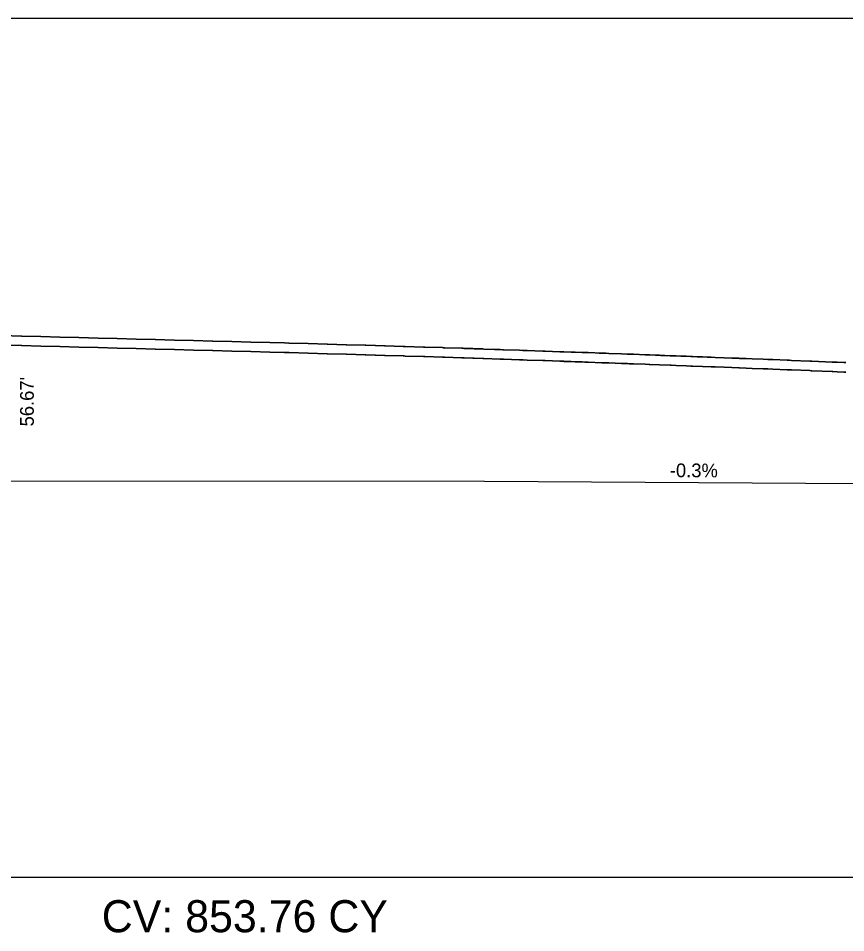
# Model space of a CAD drawing. Extents: x -26 to 4403, y -13 to 9578.
# Drawn here: x 1306.82 to 1350.15, y 6997.1 to 7045 of the extents above; entities that cross this region are included whole.
import ezdxf

# ---------------------------------------------------------------- set-up
doc = ezdxf.new("R2010")
doc.units = 0
for name, color, linetype in [('CONST_LV3', 7, 'Continuous'), ('DTM_P_FINISHED_GRADE', 7, 'Continuous'), ('DTM_X_GROUND', 7, 'Continuous'), ('XS_CELL', 7, 'Continuous'), ('XS_M_SHAPES_EARTHWORK', 7, 'Continuous'), ('XS_P_DR_GRAVEL', 7, 'Continuous'), ('XS_P_GROUND', 7, 'Continuous'), ('XS_P_TX_CLEARZONE', 7, 'Continuous'), ('XS_P_TX_FS_BS', 7, 'Continuous'), ('XS_SHEET_EW_TX_VOLUME', 7, 'Continuous')]:
    doc.layers.add(name, color=color, linetype=linetype)

msp = doc.modelspace()

# ---------------------------------------------------------------- linework, layer by layer
at = {"layer": 'CONST_LV3'}
msp.add_lwpolyline([(1305.996, 7028.38), (1306.996, 7028.354), (1307.996, 7028.327), (1308.996, 7028.301), (1309.996, 7028.274), (1310.996, 7028.248), (1311.996, 7028.221), (1312.996, 7028.195), (1313.996, 7028.169), (1314.996, 7028.142), (1315.996, 7028.116), (1316.996, 7028.089), (1317.996, 7028.063), (1318.996, 7028.036), (1319.996, 7028.01), (1320.757, 7027.99), (1320.996, 7027.983), (1320.996, 7027.983), (1320.996, 7027.983), (1321.996, 7027.956), (1321.996, 7027.956), (1321.998, 7027.956), (1322.995, 7027.928), (1322.998, 7027.928), (1323.002, 7027.928), (1323.994, 7027.9), (1324, 7027.9), (1324.007, 7027.899), (1324.991, 7027.87), (1325.006, 7027.87), (1325.014, 7027.87), (1325.025, 7027.87), (1326.004, 7027.84), (1326.015, 7027.84), (1326.021, 7027.84), (1326.504, 7027.825), (1326.546, 7027.824), (1327.029, 7027.809), (1327.079, 7027.807), (1328.037, 7027.777), (1328.047, 7027.777), (1328.104, 7027.775), (1329.044, 7027.745), (1329.071, 7027.744), (1329.132, 7027.742), (1330.051, 7027.712), (1330.103, 7027.71), (1330.105, 7027.71), (1330.161, 7027.709), (1331.056, 7027.678), (1331.142, 7027.676), (1331.192, 7027.674), (1331.632, 7027.659), (1331.753, 7027.655), (1332.189, 7027.64), (1332.223, 7027.639), (1333.062, 7027.61), (1333.247, 7027.604), (1333.255, 7027.604), (1333.46, 7027.597), (1334.287, 7027.567), (1334.314, 7027.567), (1334.405, 7027.564), (1335.187, 7027.535), (1335.319, 7027.531), (1335.394, 7027.529), (1335.597, 7027.522), (1336.35, 7027.494), (1336.486, 7027.489), (1336.668, 7027.483), (1337.031, 7027.47), (1337.239, 7027.463), (1337.592, 7027.449), (1337.741, 7027.444), (1338.409, 7027.419), (1338.713, 7027.408), (1338.815, 7027.405), (1339.032, 7027.397), (1339.657, 7027.373), (1339.851, 7027.366), (1339.889, 7027.365), (1340.461, 7027.343), (1340.964, 7027.323), (1341.006, 7027.322), (1341.52, 7027.303), (1342.038, 7027.282), (1342.132, 7027.279), (1342.37, 7027.269), (1342.89, 7027.25), (1343.113, 7027.241), (1343.32, 7027.233), (1343.79, 7027.216), (1344.186, 7027.2), (1344.546, 7027.187), (1344.589, 7027.185), (1344.928, 7027.173), (1345.257, 7027.159), (1345.828, 7027.137), (1346.066, 7027.128), (1346.328, 7027.118), (1347.092, 7027.087), (1347.205, 7027.084), (1347.397, 7027.076), (1348.345, 7027.037), (1348.384, 7027.036), (1348.444, 7027.034), (1349.459, 7026.992), (1349.484, 7026.991), (1349.704, 7026.984), (1350.05, 7026.97), (1350.15, 7026.966)], dxfattribs=at)
at = {"layer": 'DTM_P_FINISHED_GRADE'}
msp.add_lwpolyline([(1306, 7028.38), (1306.996, 7028.354), (1307, 7028.354), (1307.996, 7028.327), (1308, 7028.327), (1308.996, 7028.301), (1309, 7028.301), (1309.996, 7028.274), (1310, 7028.274), (1310.996, 7028.248), (1311, 7028.248), (1311.996, 7028.221), (1312, 7028.221), (1312.996, 7028.195), (1313, 7028.195), (1313.996, 7028.169), (1314, 7028.168), (1314.996, 7028.142), (1315, 7028.142), (1315.996, 7028.116), (1316, 7028.115), (1316.996, 7028.089), (1317, 7028.089), (1317.996, 7028.063), (1318, 7028.063), (1318.996, 7028.036), (1319, 7028.036), (1319.996, 7028.01), (1320, 7028.01), (1320.757, 7027.99), (1320.996, 7027.983), (1320.996, 7027.983), (1321, 7027.983), (1321, 7027.983), (1321.996, 7027.956), (1321.996, 7027.956), (1322, 7027.956), (1322.002, 7027.956), (1322.995, 7027.928), (1322.998, 7027.928), (1323.001, 7027.928), (1323.005, 7027.928), (1323.994, 7027.9), (1324, 7027.9), (1324.003, 7027.899), (1324.011, 7027.899), (1324.991, 7027.87), (1325.006, 7027.87), (1325.01, 7027.87), (1325.017, 7027.87), (1325.507, 7027.855), (1325.521, 7027.855), (1326.004, 7027.84), (1326.015, 7027.84), (1326.019, 7027.84), (1326.025, 7027.84), (1326.98, 7027.81), (1327.029, 7027.809), (1327.032, 7027.809), (1327.083, 7027.807), (1328.037, 7027.777), (1328.047, 7027.777), (1328.051, 7027.777), (1328.108, 7027.775), (1329.044, 7027.745), (1329.072, 7027.744), (1329.075, 7027.744), (1329.135, 7027.742), (1330.051, 7027.712), (1330.103, 7027.71), (1330.106, 7027.71), (1330.109, 7027.71), (1330.164, 7027.708), (1330.617, 7027.693), (1330.697, 7027.691), (1331.142, 7027.676), (1331.145, 7027.676), (1331.195, 7027.674), (1332.06, 7027.644), (1332.189, 7027.64), (1332.193, 7027.64), (1332.226, 7027.639), (1333.062, 7027.61), (1333.247, 7027.604), (1333.25, 7027.604), (1333.258, 7027.604), (1333.463, 7027.597), (1334.287, 7027.567), (1334.315, 7027.567), (1334.318, 7027.567), (1334.408, 7027.564), (1335.187, 7027.535), (1335.319, 7027.531), (1335.394, 7027.529), (1335.397, 7027.528), (1335.774, 7027.515), (1335.983, 7027.507), (1336.35, 7027.494), (1336.486, 7027.489), (1336.489, 7027.489), (1336.671, 7027.483), (1337.38, 7027.456), (1337.592, 7027.449), (1337.595, 7027.449), (1337.744, 7027.444), (1338.409, 7027.419), (1338.713, 7027.408), (1338.716, 7027.408), (1338.817, 7027.405), (1339.035, 7027.397), (1339.657, 7027.373), (1339.851, 7027.366), (1339.853, 7027.366), (1339.892, 7027.365), (1340.391, 7027.345), (1340.964, 7027.323), (1341.006, 7027.322), (1341.008, 7027.322), (1341.274, 7027.312), (1341.788, 7027.292), (1342.038, 7027.282), (1342.132, 7027.279), (1342.134, 7027.278), (1342.656, 7027.26), (1343.113, 7027.241), (1343.32, 7027.233), (1343.322, 7027.233), (1343.792, 7027.216), (1344.186, 7027.2), (1344.546, 7027.187), (1344.589, 7027.185), (1344.59, 7027.185), (1344.929, 7027.172), (1345.258, 7027.159), (1345.828, 7027.137), (1345.829, 7027.137), (1346.067, 7027.128), (1346.328, 7027.118), (1347.092, 7027.087), (1347.093, 7027.087), (1347.206, 7027.084), (1347.305, 7027.08), (1348.279, 7027.04), (1348.345, 7027.037), (1348.384, 7027.036), (1348.384, 7027.036), (1349.433, 7026.993), (1349.484, 7026.991), (1349.704, 7026.984), (1349.704, 7026.984), (1350.05, 7026.97), (1350.15, 7026.966)], dxfattribs=at)
at = {"layer": 'DTM_X_GROUND'}
msp.add_lwpolyline([(1172.393, 7016.843), (1201.803, 7015.398), (1214.564, 7014.215), (1224.971, 7013.522), (1232.816, 7013.949), (1243.916, 7015.546), (1247.514, 7017.177), (1252.067, 7016.906), (1267.338, 7018.231), (1284.701, 7020.032), (1288.812, 7020.146), (1295.897, 7020.771), (1296.81, 7020.815), (1306.145, 7020.771), (1331.242, 7020.749), (1362.053, 7020.566), (1388.429, 7020.524), (1400, 7020.43)], dxfattribs=at)
at = {"layer": 'XS_CELL'}
msp.add_line((1250, 7000), (1400, 7000), dxfattribs=at)
at = {"layer": 'XS_M_SHAPES_EARTHWORK'}
for points in [[(1350.15, 7026.466), (1350.05, 7026.47), (1349.704, 7026.484), (1349.484, 7026.491), (1349.433, 7026.493), (1348.384, 7026.536), (1348.345, 7026.537), (1348.279, 7026.54), (1347.305, 7026.58), (1347.206, 7026.584), (1347.092, 7026.587), (1346.328, 7026.618), (1346.067, 7026.628), (1345.829, 7026.637), (1345.828, 7026.637), (1345.258, 7026.659), (1344.929, 7026.672), (1344.59, 7026.685), (1344.589, 7026.685), (1344.546, 7026.687), (1344.186, 7026.7), (1343.792, 7026.716), (1343.322, 7026.733), (1343.32, 7026.733), (1343.113, 7026.741), (1342.656, 7026.76), (1342.134, 7026.778), (1342.132, 7026.779), (1342.038, 7026.782), (1341.788, 7026.792), (1341.274, 7026.812), (1341.008, 7026.822), (1341.006, 7026.822), (1340.964, 7026.823), (1340.391, 7026.845), (1339.892, 7026.865), (1339.853, 7026.866), (1339.851, 7026.866), (1339.657, 7026.873), (1339.035, 7026.897), (1338.817, 7026.905), (1338.716, 7026.908), (1338.713, 7026.908), (1338.409, 7026.919), (1337.744, 7026.944), (1337.595, 7026.949), (1337.592, 7026.949), (1337.38, 7026.956), (1336.671, 7026.983), (1336.489, 7026.989), (1336.486, 7026.989), (1336.35, 7026.994), (1335.983, 7027.007), (1335.774, 7027.015), (1335.397, 7027.028), (1335.394, 7027.029), (1335.319, 7027.031), (1335.187, 7027.035), (1334.408, 7027.064), (1334.318, 7027.067), (1334.315, 7027.067), (1334.287, 7027.067), (1333.463, 7027.097), (1333.258, 7027.104), (1333.25, 7027.104), (1333.247, 7027.104), (1333.062, 7027.11), (1332.226, 7027.139), (1332.193, 7027.14), (1332.189, 7027.14), (1332.06, 7027.144), (1331.195, 7027.174), (1331.145, 7027.176), (1331.142, 7027.176), (1330.697, 7027.191), (1330.617, 7027.193), (1330.164, 7027.208), (1330.109, 7027.21), (1330.106, 7027.21), (1330.103, 7027.21), (1330.051, 7027.212), (1329.135, 7027.242), (1329.075, 7027.244), (1329.072, 7027.244), (1329.044, 7027.245), (1328.108, 7027.275), (1328.051, 7027.277), (1328.047, 7027.277), (1328.037, 7027.277), (1327.083, 7027.307), (1327.032, 7027.309), (1327.029, 7027.309), (1326.98, 7027.31), (1326.025, 7027.34), (1326.019, 7027.34), (1326.015, 7027.34), (1326.004, 7027.34), (1325.521, 7027.355), (1325.507, 7027.355), (1325.017, 7027.37), (1325.01, 7027.37), (1325.006, 7027.37), (1324.991, 7027.37), (1324.011, 7027.399), (1324.003, 7027.399), (1324, 7027.4), (1323.994, 7027.4), (1323.005, 7027.428), (1323.001, 7027.428), (1322.998, 7027.428), (1322.995, 7027.428), (1322.002, 7027.456), (1322, 7027.456), (1321.996, 7027.456), (1321, 7027.483), (1320.996, 7027.483), (1320.757, 7027.49), (1320, 7027.51), (1319.996, 7027.51), (1319, 7027.536), (1318.996, 7027.536), (1318, 7027.563), (1317.996, 7027.563), (1317, 7027.589), (1316.996, 7027.589), (1316, 7027.615), (1315.996, 7027.616), (1315, 7027.642), (1314.996, 7027.642), (1314, 7027.668), (1313.996, 7027.669), (1313, 7027.695), (1312.996, 7027.695), (1312, 7027.721), (1311.996, 7027.721), (1311, 7027.748), (1310.996, 7027.748), (1310, 7027.774), (1309.996, 7027.774), (1309, 7027.801), (1308.996, 7027.801), (1308, 7027.827), (1307.996, 7027.827), (1307, 7027.854), (1306.996, 7027.854), (1306, 7027.88)], [(1252.067, 7016.906), (1267.338, 7018.231), (1284.701, 7020.032), (1288.812, 7020.146), (1295.897, 7020.771), (1296.81, 7020.815), (1306.145, 7020.771), (1331.242, 7020.749), (1362.053, 7020.566)]]:
    msp.add_lwpolyline(points, dxfattribs=at)
at = {"layer": 'XS_P_DR_GRAVEL'}
for points in [[(1350.15, 7026.966), (1350.05, 7026.97), (1349.704, 7026.984), (1349.704, 7026.984), (1349.484, 7026.991), (1349.433, 7026.993), (1348.384, 7027.036), (1348.384, 7027.036), (1348.345, 7027.037), (1348.279, 7027.04), (1347.305, 7027.08), (1347.206, 7027.084), (1347.093, 7027.087), (1347.092, 7027.087), (1346.328, 7027.118), (1346.067, 7027.128), (1345.829, 7027.137), (1345.828, 7027.137), (1345.258, 7027.159), (1344.929, 7027.172), (1344.59, 7027.185), (1344.589, 7027.185), (1344.546, 7027.187), (1344.186, 7027.2), (1343.792, 7027.216), (1343.322, 7027.233), (1343.32, 7027.233), (1343.113, 7027.241), (1342.656, 7027.26), (1342.134, 7027.278), (1342.132, 7027.279), (1342.038, 7027.282), (1341.788, 7027.292), (1341.274, 7027.312), (1341.008, 7027.322), (1341.006, 7027.322), (1340.964, 7027.323), (1340.391, 7027.345), (1339.892, 7027.365), (1339.853, 7027.366), (1339.851, 7027.366), (1339.657, 7027.373), (1339.035, 7027.397), (1338.817, 7027.405), (1338.716, 7027.408), (1338.713, 7027.408), (1338.409, 7027.419), (1337.744, 7027.444), (1337.595, 7027.449), (1337.592, 7027.449), (1337.38, 7027.456), (1336.671, 7027.483), (1336.489, 7027.489), (1336.486, 7027.489), (1336.35, 7027.494), (1335.983, 7027.507), (1335.774, 7027.515), (1335.397, 7027.528), (1335.394, 7027.529), (1335.319, 7027.531), (1335.187, 7027.535), (1334.408, 7027.564), (1334.318, 7027.567), (1334.315, 7027.567), (1334.287, 7027.567), (1333.463, 7027.597), (1333.258, 7027.604), (1333.25, 7027.604), (1333.247, 7027.604), (1333.062, 7027.61), (1332.226, 7027.639), (1332.193, 7027.64), (1332.189, 7027.64), (1332.06, 7027.644), (1331.195, 7027.674), (1331.145, 7027.676), (1331.142, 7027.676), (1330.697, 7027.691), (1330.617, 7027.693), (1330.164, 7027.708), (1330.109, 7027.71), (1330.106, 7027.71), (1330.103, 7027.71), (1330.051, 7027.712), (1329.135, 7027.742), (1329.075, 7027.744), (1329.072, 7027.744), (1329.044, 7027.745), (1328.108, 7027.775), (1328.051, 7027.777), (1328.047, 7027.777), (1328.037, 7027.777), (1327.083, 7027.807), (1327.032, 7027.809), (1327.029, 7027.809), (1326.98, 7027.81), (1326.025, 7027.84), (1326.019, 7027.84), (1326.015, 7027.84), (1326.004, 7027.84), (1325.521, 7027.855), (1325.507, 7027.855), (1325.017, 7027.87), (1325.01, 7027.87), (1325.006, 7027.87), (1324.991, 7027.87), (1324.011, 7027.899), (1324.003, 7027.899), (1324, 7027.9), (1323.994, 7027.9), (1323.005, 7027.928), (1323.001, 7027.928), (1322.998, 7027.928), (1322.995, 7027.928), (1322.002, 7027.956), (1322, 7027.956), (1321.996, 7027.956), (1321.996, 7027.956), (1321, 7027.983), (1321, 7027.983), (1320.996, 7027.983), (1320.996, 7027.983), (1320.757, 7027.99), (1320.757, 7027.99), (1320, 7028.01), (1319.996, 7028.01), (1319, 7028.036), (1318.996, 7028.036), (1318, 7028.063), (1317.996, 7028.063), (1317, 7028.089), (1316.996, 7028.089), (1316, 7028.115), (1315.996, 7028.116), (1315, 7028.142), (1314.996, 7028.142), (1314, 7028.168), (1313.996, 7028.169), (1313, 7028.195), (1312.996, 7028.195), (1312, 7028.221), (1311.996, 7028.221), (1311, 7028.248), (1310.996, 7028.248), (1310, 7028.274), (1309.996, 7028.274), (1309, 7028.301), (1308.996, 7028.301), (1308, 7028.327), (1307.996, 7028.327), (1307, 7028.354), (1306.996, 7028.354), (1306, 7028.38)], [(1306, 7027.88), (1306.996, 7027.854), (1307, 7027.854), (1307.996, 7027.827), (1308, 7027.827), (1308.996, 7027.801), (1309, 7027.801), (1309.996, 7027.774), (1310, 7027.774), (1310.996, 7027.748), (1311, 7027.748), (1311.996, 7027.721), (1312, 7027.721), (1312.996, 7027.695), (1313, 7027.695), (1313.996, 7027.669), (1314, 7027.668), (1314.996, 7027.642), (1315, 7027.642), (1315.996, 7027.616), (1316, 7027.615), (1316.996, 7027.589), (1317, 7027.589), (1317.996, 7027.563), (1318, 7027.563), (1318.996, 7027.536), (1319, 7027.536), (1319.996, 7027.51), (1320, 7027.51), (1320.757, 7027.49), (1320.757, 7027.49), (1320.996, 7027.483), (1320.996, 7027.483), (1321, 7027.483), (1321, 7027.483), (1321.996, 7027.456), (1321.996, 7027.456), (1322, 7027.456), (1322.002, 7027.456), (1322.995, 7027.428), (1322.998, 7027.428), (1323.001, 7027.428), (1323.005, 7027.428), (1323.994, 7027.4), (1324, 7027.4), (1324.003, 7027.399), (1324.011, 7027.399), (1324.991, 7027.37), (1325.006, 7027.37), (1325.01, 7027.37), (1325.017, 7027.37), (1325.507, 7027.355), (1325.521, 7027.355), (1326.004, 7027.34), (1326.015, 7027.34), (1326.019, 7027.34), (1326.025, 7027.34), (1326.98, 7027.31), (1327.029, 7027.309), (1327.032, 7027.309), (1327.083, 7027.307), (1328.037, 7027.277), (1328.047, 7027.277), (1328.051, 7027.277), (1328.108, 7027.275), (1329.044, 7027.245), (1329.072, 7027.244), (1329.075, 7027.244), (1329.135, 7027.242), (1330.051, 7027.212), (1330.103, 7027.21), (1330.106, 7027.21), (1330.109, 7027.21), (1330.164, 7027.208), (1330.617, 7027.193), (1330.697, 7027.191), (1331.142, 7027.176), (1331.145, 7027.176), (1331.195, 7027.174), (1332.06, 7027.144), (1332.189, 7027.14), (1332.193, 7027.14), (1332.226, 7027.139), (1333.062, 7027.11), (1333.247, 7027.104), (1333.25, 7027.104), (1333.258, 7027.104), (1333.463, 7027.097), (1334.287, 7027.067), (1334.315, 7027.067), (1334.318, 7027.067), (1334.408, 7027.064), (1335.187, 7027.035), (1335.319, 7027.031), (1335.394, 7027.029), (1335.397, 7027.028), (1335.774, 7027.015), (1335.983, 7027.007), (1336.35, 7026.994), (1336.486, 7026.989), (1336.489, 7026.989), (1336.671, 7026.983), (1337.38, 7026.956), (1337.592, 7026.949), (1337.595, 7026.949), (1337.744, 7026.944), (1338.409, 7026.919), (1338.713, 7026.908), (1338.716, 7026.908), (1338.817, 7026.905), (1339.035, 7026.897), (1339.657, 7026.873), (1339.851, 7026.866), (1339.853, 7026.866), (1339.892, 7026.865), (1340.391, 7026.845), (1340.964, 7026.823), (1341.006, 7026.822), (1341.008, 7026.822), (1341.274, 7026.812), (1341.788, 7026.792), (1342.038, 7026.782), (1342.132, 7026.779), (1342.134, 7026.778), (1342.656, 7026.76), (1343.113, 7026.741), (1343.32, 7026.733), (1343.322, 7026.733), (1343.792, 7026.716), (1344.186, 7026.7), (1344.546, 7026.687), (1344.589, 7026.685), (1344.59, 7026.685), (1344.929, 7026.672), (1345.258, 7026.659), (1345.828, 7026.637), (1345.829, 7026.637), (1346.067, 7026.628), (1346.328, 7026.618), (1347.092, 7026.587), (1347.093, 7026.587), (1347.206, 7026.584), (1347.305, 7026.58), (1348.279, 7026.54), (1348.345, 7026.537), (1348.384, 7026.536), (1348.384, 7026.536), (1349.433, 7026.493), (1349.484, 7026.491), (1349.704, 7026.484), (1349.704, 7026.484), (1350.05, 7026.47), (1350.15, 7026.466)]]:
    msp.add_lwpolyline(points, dxfattribs=at)
at = {"layer": 'XS_P_GROUND'}
msp.add_line((1250, 7045), (1380, 7045), dxfattribs=at)

# ---------------------------------------------------------------- texts
at = {"layer": 'XS_P_TX_CLEARZONE'}
msp.add_text("56.67'", height=0.72, rotation=90, dxfattribs=at).set_placement((1307.635, 7023.62))
msp.add_text("56.67'", height=0.72, rotation=90, dxfattribs=at).set_placement((1307.635, 7023.62))
msp.add_text("56.67'", height=0.72, rotation=90, dxfattribs=at).set_placement((1307.635, 7023.62))
at = {"layer": 'XS_P_TX_FS_BS'}
msp.add_text('-0.3%', height=0.72, rotation=359.8151, dxfattribs=at).set_placement((1340.938, 7020.96))
msp.add_text('-0.3%', height=0.72, rotation=359.8151, dxfattribs=at).set_placement((1340.938, 7020.96))
msp.add_text('-0.3%', height=0.72, rotation=359.8151, dxfattribs=at).set_placement((1340.938, 7020.96))
at = {"layer": 'XS_SHEET_EW_TX_VOLUME'}
msp.add_text('CV: 853.76 CY', height=1.68, dxfattribs=at).set_placement((1311.192, 6997.12))

doc.saveas('drawing.dxf')
